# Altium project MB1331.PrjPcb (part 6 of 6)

## Sheet Power_MCU.SchDoc: MCU Power
size A4; Date: Not used; ApprovedBy: Not used; CheckedBy: Not used; Author: Not used; CompanyName: STMicroelectronics; DrawnBy: Not used; Engineer: Not used; Organization: Not used; Address1: Not used; Address2: Not used; Address3: Not used; Address4: Not used; DocumentNumber: Not used; Revision: Not used; SheetNumber: 21; SheetTotal: 23
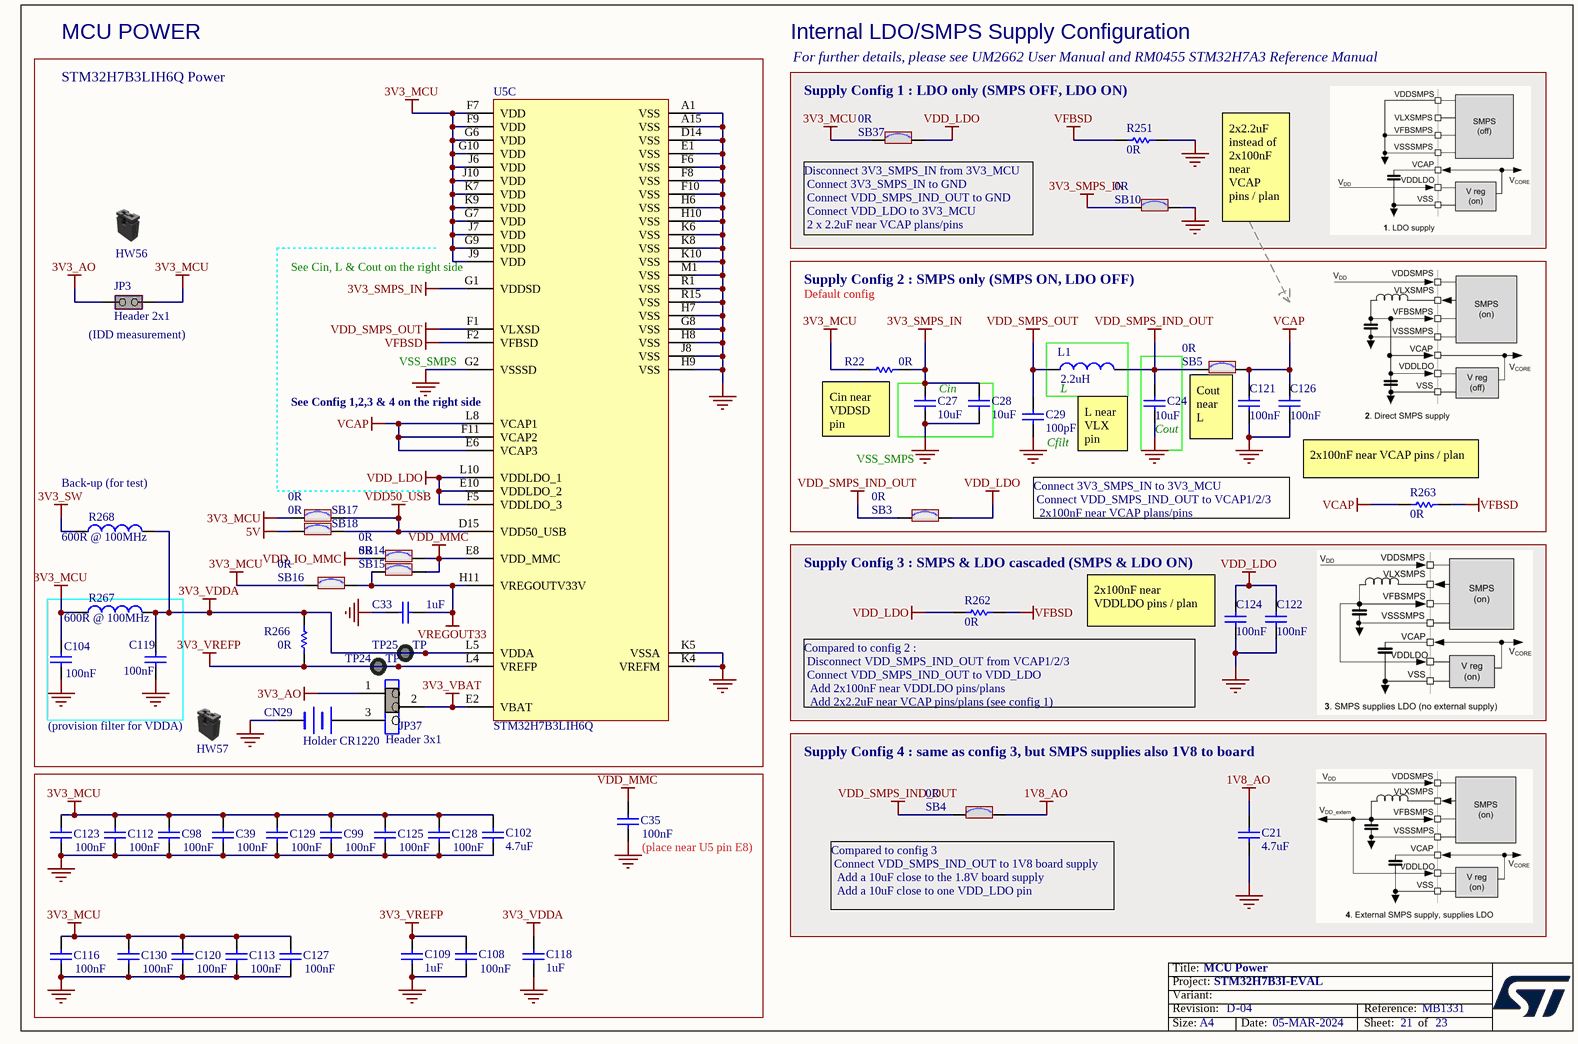
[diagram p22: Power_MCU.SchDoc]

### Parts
C21  value 4.7uF  [C0603]  (hidden comment: Capacitor)
C24  value 10uF  [C0603]  (hidden comment: Capacitor)
C27  value 10uF  [C0402]  (hidden comment: Capacitor)
C28  value 10uF  [C0402]  (hidden comment: Capacitor)
C29  value 100pF  [C0402]  (hidden comment: Capacitor)
C33  value 1uF  [C0603]  (hidden comment: Capacitor)
C35  value 100nF  [C0402]  (hidden comment: Capacitor)
C39  value 100nF  [C0402]  (hidden comment: Capacitor)
C98  value 100nF  [C0402]  (hidden comment: Capacitor)
C99  value 100nF  [C0402]  (hidden comment: Capacitor)
C102  value 4.7uF  [C0603]  (hidden comment: Capacitor)
C104  value 100nF  [C0402]  (hidden comment: Capacitor)
C108  value 100nF  [C0402]  (hidden comment: Capacitor)
C109  value 1uF  [C0402]  (hidden comment: Capacitor)
C112  value 100nF  [C0402]  (hidden comment: Capacitor)
C113  value 100nF  [C0402]  (hidden comment: Capacitor)
C116  value 100nF  [C0402]  (hidden comment: Capacitor)
C118  value 1uF  [C0402]  (hidden comment: Capacitor)
C119  value 100nF  [C0402]  (hidden comment: Capacitor)
C120  value 100nF  [C0402]  (hidden comment: Capacitor)
C121  value 100nF  [C0402]  (hidden comment: Capacitor)
C122  value 100nF  [C0402]  (hidden comment: Capacitor)
C123  value 100nF  [C0402]  (hidden comment: Capacitor)
C124  value 100nF  [C0402]  (hidden comment: Capacitor)
C125  value 100nF  [C0402]  (hidden comment: Capacitor)
C126  value 100nF  [C0402]  (hidden comment: Capacitor)
C127  value 100nF  [C0402]  (hidden comment: Capacitor)
C128  value 100nF  [C0402]  (hidden comment: Capacitor)
C129  value 100nF  [C0402]  (hidden comment: Capacitor)
C130  value 100nF  [C0402]  (hidden comment: Capacitor)
CN29  value Holder CR1220  [BAT_HARWIN_S8411-45R_SMD_2P]  (hidden comment: BATTERY HOLDER)
HW56  Shunt Black 2.54mm  (value not drawn)  (mechanical)
HW57  Shunt Black 2.54mm  (value not drawn)  (mechanical)
JP3  value Header 2x1  [CON_SAMTEC_TSW-102-07-G-S]  (hidden comment: Jumper_Header 2x1 Fitted)
JP37  value Header 3x1  [CON_SAMTEC_TSW-103-07-F-S]  (hidden comment: Jumper_Header 3x1 Fitted 1-2)
L1  value 2.2uH  [L0805_H0P9]  (hidden comment: Inductor)
R22  value 0R  [R0603]  (hidden comment: Resistor)
R251  value 0R  [R0402]  (hidden comment: Resistor)
R262  value 0R  [R0402]  (hidden comment: Resistor)
R263  value 0R  [R0402]  (hidden comment: Resistor)
R266  value 0R  [R0603]  (hidden comment: Resistor)
R267  value 600R @ 100MHz  [L0603]  (hidden comment: BEAD)
R268  value 600R @ 100MHz  [L0603]  (hidden comment: BEAD)
SB3  value 0R  [SOLDER-BRIDGE_R0603-0R]  (hidden comment: SB_ON)
SB4  value 0R  [SOLDER-BRIDGE_R0603-0R]  (hidden comment: SB_ON)
SB5  value 0R  [SOLDER-BRIDGE_R0603-0R]  (hidden comment: SB_ON)
SB10  value 0R  [SOLDER-BRIDGE_R0603-0R]  (hidden comment: SB_ON)
SB14  value 0R  [SOLDER-BRIDGE_R0603-0R]  (hidden comment: SB_ON)
SB15  value 0R  [SOLDER-BRIDGE_R0603-0R]  (hidden comment: SB_ON)
SB16  value 0R  [SOLDER-BRIDGE_R0603-0R]  (hidden comment: SB_ON)
SB17  value 0R  [SOLDER-BRIDGE_R0603-0R]  (hidden comment: SB_ON)
SB18  value 0R  [SOLDER-BRIDGE_R0603-0R]  (hidden comment: SB_ON)
SB37  value 0R  [SOLDER-BRIDGE_R0603-0R]  (hidden comment: SB_ON)
TP24  value TP  [TP_PTH_1MM_2MM]  (hidden comment: Test_Point_PTH_1mm_2mm)  (no BOM)
TP25  value TP  [TP_PTH_1MM_2MM]  (hidden comment: Test_Point_PTH_1mm_2mm)  (no BOM)
U5  value STM32H7B3LIH6Q  [ICC_TFBGA225_13X13_STM32H7B3NIH6Q_P080__SOCKET_IRONWOOD_CS1222291MF_REV-A_WITHOUT-3D-SOCKET]  (hidden comment: STM32H7B3NIH6Q)  (part C of 3)

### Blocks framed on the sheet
MCU POWER: C33 C104 C119 CN29 HW56 HW57 JP3 JP37 R266-R268 SB14-SB18 TP24 TP25 U5
Supply Config 1 : LDO only (SMPS OFF, LDO ON): R251 SB10 SB37
Supply Config 2 : SMPS only (SMPS ON, LDO OFF): C29 C121 C126 R22 R263 SB3 SB5
L: L1
Cin: C27 C28
Cout: C24
Supply Config 3 : SMPS & LDO cascaded (SMPS & LDO ON): C122 C124 R262
(place near U5 pin E8): C35 C39 C98 C99 C102 C108 C109 C112 C113 C116 C118 C120 C123 C125 C127-C130

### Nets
1V8_AO: C21.2 SB4.2
3V3_AO: JP3.1(COMMON) JP37.1
3V3_MCU: C39.1 C98.1 C99.1 C102.2 C104.1 C112.1 C113.1 C116.1 C120.1 C123.1 C125.1 C127.1 C128.1 C129.1 C130.1 JP3.2(NO) R22.2 R267.1 SB16.1 SB17.2 SB37.2 U5.F7(VDD) U5.F9(VDD) U5.G6(VDD) U5.G7(VDD) U5.G9(VDD) U5.G10(VDD) U5.J6(VDD) U5.J7(VDD) U5.J9(VDD) U5.J10(VDD) U5.K7(VDD) U5.K9(VDD)
3V3_SMPS_IN: C27.2 C28.2 R22.1 SB10.2 U5.G1(VDDSD)
3V3_SW: R268.1
3V3_VBAT: JP37.2 U5.E2(VBAT)
3V3_VDDA: C118.2 C119.1 R266.1 R267.2 R268.2 TP25.1 U5.L5(VDDA)
3V3_VREFP: C108.2 C109.2 R266.2 TP24.1 U5.L4(VREFP)
5V: SB18.2
GND: C21.1 C24.1 C27.1 C28.1 C29.1 C33.2 C35.2 C39.2 C98.2 C99.2 C102.1 C104.2 C108.1 C109.1 C112.2 C113.2 C116.2 C118.1 C119.2 C120.2 C121.2 C122.2 C123.2 C124.2 C125.2 C126.2 C127.2 C128.2 C129.2 C130.2 CN29.2(-) R251.2 SB10.1 U5.A1(VSS) U5.A15(VSS) U5.D14(VSS) U5.E1(VSS) U5.F6(VSS) U5.F8(VSS) U5.F10(VSS) U5.G2(VSSSD) U5.G8(VSS) U5.H6(VSS) U5.H7(VSS) U5.H8(VSS) U5.H9(VSS) U5.H10(VSS) U5.J8(VSS) U5.K4(VREFM) U5.K5(VSSA) U5.K6(VSS) U5.K8(VSS) U5.K10(VSS) U5.M1(VSS) U5.R1(VSS) U5.R15(VSS)
VCAP: C121.1 C126.1 R263.1 SB5.1 U5.E6(VCAP3) U5.F11(VCAP2) U5.L8(VCAP1)
VDD50_USB: SB17.1 SB18.1 U5.D15(VDD50_USB)
VDD_IO_MMC: SB14.1
VDD_LDO: C122.1 C124.1 R262.1 SB3.1 SB37.1 U5.E10(VDDLDO_2) U5.F5(VDDLDO_3) U5.L10(VDDLDO_1)
VDD_MMC: C35.1 SB14.2 SB15.1 U5.E8(VDD_MMC)
VDD_SMPS_IND_OUT: C24.2 L1.2 SB3.2 SB4.1 SB5.2
VDD_SMPS_OUT: C29.2 L1.1 U5.F1(VLXSD)
VFBSD: R251.1 R262.2 R263.2 U5.F2(VFBSD)
VREGOUT33: C33.1 SB15.2 SB16.2 U5.H11(VREGOUTV33V)
NetCN29_1: CN29.1(+) JP37.3

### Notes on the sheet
- Internal LDO/SMPS Supply Configuration
- STM32H7B3LIH6Q Power
- For further details, please see UM2662 User Manual and RM0455 STM32H7A3 Reference Manual
- (near SB37) Disconnect 3V3_SMPS_IN from 3V3_MCU
  Connect 3V3_SMPS_IN to GND
  Connect VDD_SMPS_IND_OUT to GND
  Connect VDD_LDO to 3V3_MCU
  2 x 2.2uF near VCAP plans/pins
- 2x2.2uF instead of 2x100nF near VCAP pins / plan
- (near U5) See Cin, L & Cout on the right side
- Default config
- (near JP3) (IDD measurement)
- (near U5) VSS_SMPS
- (near U5) See Config 1,2,3 & 4 on the right side
- (near R22) Cin near VDDSD pin
- (near C29) Cfilt
- L near VLX pin
- (near SB5) Cout near L
- (near R268) Back-up (for test)
- VSS_SMPS
- Connect 3V3_SMPS_IN to 3V3_MCU
  Connect VDD_SMPS_IND_OUT to VCAP1/2/3
  2x100nF near VCAP plans/pins
- 2x100nF near VCAP pins / plan
- (near C124) 2x100nF near VDDLDO pins / plan
- Compared to config 2 :
  Disconnect VDD_SMPS_IND_OUT from VCAP1/2/3
  Connect VDD_SMPS_IND_OUT to VDD_LDO
  Add 2x100nF near VDDLDO pins/plans
  Add 2x2.2uF near VCAP pins/plans (see config 1)
- (near HW57) (provision filter for VDDA)
- Supply Config 4 : same as config 3, but SMPS supplies also 1V8 to board
- (near SB4) Compared to config 3
  Connect VDD_SMPS_IND_OUT to 1V8 board supply
  Add a 10uF close to the 1.8V board supply
  Add a 10uF close to one VDD_LDO pin

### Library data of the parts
C21 C102 = MCD-04044: Capacitor, MLCC, 4.7uF, 10V, X5R, 20%, 0603, T=0.8mm; Manufacturer_Part_Number: C0603C475M8PAC7040; Manufacturer: KEMET CORPORATION; Part_Preference: Recommended; Component_Country_Of_Origin: Mexico; ShowFields: YES; ID: 6160
C24 = MCD-01341: Capacitor, MLCC, 10uF, 6V3, X5R, 20%, 0603, T=0,8mm; Manufacturer_Part_Number: GRM188R60J106ME47D; Manufacturer: MURATA; Part_Preference: Recommended; Provided_By: SUBCO; ECCN_US: EAR99; ECCN_EU: NEC; Component_Country_Of_Origin: Japan°°; ID: 3441; ShowFields: YES
C27 C28 = MCD-01716: Capacitor, MLCC, 10uF, 6V3, X5R, 20%, 0402, T=0.5mm; Manufacturer_Part_Number: CC0402MRX5R5BB106; Manufacturer: YAGEO; Part_Preference: Recommended; Provided_By: SUBCO; Component_Country_Of_Origin: China; ID: 3816; ShowFields: YES
C29 = MCD-00205: Capacitor, MLCC, 100pF, 50V, NPO, 5%, 0402, T=0,5mm; Manufacturer_Part_Number: CC0402JRNPO9BN101; Manufacturer: YAGEO; Part_Preference: Recommended; Provided_By: SUBCO; ECCN_US: EAR99; ECCN_EU: NEC; Component_Country_Of_Origin: China; ID: 2658; ShowFields: YES
C33 = MCD-00010: Capacitor, MLCC, 1uF, 16V, X5R, 10%, 0603, T=0,8mm; Manufacturer_Part_Number: CC0603KRX5R7BB105; Manufacturer: YAGEO; Part_Preference: Recommended; Provided_By: SUBCO; ECCN_US: EAR99; ECCN_EU: NEC; Component_Country_Of_Origin: China; ID: 2470; Order_Code_RS: 2370680; ShowFields: YES
C35 C39 C98 C99 C104 C108 C112 C113 C116 C119-C130 = MCD-00006: Capacitor, MLCC, 100nF, 16V, X7R, 10%, 0402, T=0.5mm; Manufacturer_Part_Number: CC0402KRX7R7BB104; Manufacturer: YAGEO; Alternate_Manufacturer_Part_Number: GCM155R71C104KA55D; Alternate_Manufacturer: MURATA; Part_Preference: Recommended; Partial_Alternate_Internal_Part_Number: MCD-03299; Provided_By: SUBCO; ECCN_US: EAR99; ECCN_EU: NEC; Component_Country_Of_Origin: China; ID: 2474; Order_Code_RS: 9402047; ShowFields: YES
C109 C118 = MCD-00095: Capacitor, MLCC, 1uF, 6V3, X5R, 10%, 0402, T=0,5mm; Manufacturer_Part_Number: GRM155R61E105KA12; Manufacturer: MURATA; Alternate_Manufacturer_Part_Number: GRM155R60J105KE19; Part_Preference: Recommended; Provided_By: SUBCO; ECCN_US: EAR99; ECCN_EU: NEC; Component_Country_Of_Origin: Japan°°; ID: 2772; Order_Code_RS: 2218855; ShowFields: YES
CN29 = MCD-00558: Battery Coin Cell holder, CR1220_12mm, Height 4.25mm; Part_Type: Connector; Manufacturer_Part_Number: S8411-45R; Manufacturer: HARWIN; Part_Preference: Recommended; Provided_By: SUBCO; Component_Country_Of_Origin: Taiwan; ID: 3187; ShowFields: YES
HW56 HW57 = MCD-00043: SHUNT 2.54mm BLACK; Part_Type: Misc; Manufacturer: SAMTEC; Alternate_Manufacturer_Part_Number: 316102S111A; Alternate_Manufacturer: JIUBABA; Full_Alternate_Internal_Part_Number: MCD-02388; Manufacturer_HQ_COO: Unknown; Part_Preference: Recommended; Partial_Alternate_Internal_Part_Number: MCD-01849; Value: SNT-100-BK-G; Provided_By: SUBCO; Alternate_EMS: A; Component_Country_Of_Origin: China, Costa Rica, Malaysia, USA, Vietnam; ID: 2551; Order_Code_RS: 158-7784; ShowFields: YES
JP3 = MCD-00683: Header, 2x1, 2,54mm, VR, TH, Height 5.84mm/2.54mm - Shunt Fitted by default; Part_Type: Connector; Manufacturer_Part_Number: TSW-102-07-G-S; Manufacturer: SAMTEC; Alternate_Manufacturer_Part_Number: 313102S111116; Alternate_Manufacturer: LIANYI; Full_Alternate_Internal_Part_Number: MCD-02389; Part_Preference: Recommended; Partial_Alternate_Internal_Part_Number: MCD-02957, MCD-03720; Provided_By: SUBCO; Component_Country_Of_Origin: China, Costa Rica, Malaysia, USA, Vietnam; ID: 3057; Order_Code_RS: 155-5312; ShowFields: YES
JP37 = MCD-00684: Header, 3x1, 2,54mm, VR, TH, Height 5.84mm/2.54mm - Shunt Fitted 1-2 by default; Part_Type: Connector; Manufacturer_Part_Number: TSW-103-07-F-S; Manufacturer: SAMTEC; Part_Preference: Recommended; Partial_Alternate_Internal_Part_Number: MCD-03595, MCD-03723; Provided_By: SUBCO; Alternate_EMS: A; Component_Country_Of_Origin: China, Costa Rica, Malaysia, USA, Vietnam; ID: 3059; Order_Code_RS: 161-2248; ShowFields: YES
L1 = MCD-01340: Inductor, 2.2uH, 20%, Isat 1.2A, DCR 0.228Ohm, 0805; Manufacturer_Part_Number: DFE201210U-2R2M=P2; Manufacturer: MURATA; Part_Preference: Recommended; Provided_By: SUBCO; Component_Country_Of_Origin: Japan°°; ID: 3440; ShowFields: YES
R22 R266 = MCD-00056: Resistor,0R,0603,5%,1/10W; Manufacturer_Part_Number: RC0603JR-070RL; Manufacturer: YAGEO; Part_Preference: Recommended; Provided_By: SUBCO; ECCN_US: EAR99; ECCN_EU: NEC; Component_Country_Of_Origin: China; ID: 2536; Order_Code_RS: 9233130RL; ShowFields: YES
R251 R262 R263 = MCD-00052: Resistor,0R,0402,5%,1/16W; Manufacturer_Part_Number: RC0402JR-070RL; Manufacturer: YAGEO; Part_Preference: Recommended; Provided_By: SUBCO; ECCN_US: EAR99; ECCN_EU: NEC; Component_Country_Of_Origin: China; ID: 2540; Order_Code_RS: 9232516RL; ShowFields: YES
R267 R268 = MCD-00047: SMD Chip ferrite bead, 600R@100MHz +/-25%, 350mA, 500mohm DC, 0603, T=0.8mm; Part_Type: Inductor; Manufacturer_Part_Number: FCM1608KF-601T03; Manufacturer: TAI-TECH; Part_Preference: Recommended; Partial_Alternate_Internal_Part_Number: MCD-02959; Provided_By: SUBCO; Component_Country_Of_Origin: Unknown; ID: 2546; ShowFields: YES
SB3-SB5 SB10 SB14-SB18 SB37 = MCD-00071: Solder Bridge ON; Part_Type: Resistor; Manufacturer_Part_Number: RC0603JR-070RL; Manufacturer: YAGEO; Manufacturer_HQ_COO: Unknown; Part_Preference: Recommended; Provided_By: SUBCO; Component_Country_Of_Origin: China; ID: 2521; Order_Code_RS: 199-5647; ShowFields: YES
TP24 TP25 = MCD-01506: Test Point trought hole 1mm/2mm; Part_Type: Misc; Part_Preference: Recommended; Component_Country_Of_Origin: Unknown; ID: 3606; ShowFields: YES
U5 = MCD-01929: STM32H7B3LIH6Q (crypto),TFBGA 225, 13x13 0.8; Part_Type: IC; Manufacturer: STMICROELECTRONICS; BMS_Part_Number: 9175358; Manufacturer_HQ_COO: EU; Part_Preference: Recommended; ECCN_US: 5A992C; ECCN_EU: 5A002A4; Provided_By: SUBCO with ST control; Component_Country_Of_Origin: Philippines; ID: 4029; Order_Code_RS: 201-4447; ShowFields: YES

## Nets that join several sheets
1V8_AO: Audio_Codec (SB25.1), Power_Board (SB22.2 TP12.1), USB_OTG_HS_externalPHY (R274.1), Power_MCU (C21.2 SB4.2)
1V8_SW: Audio_Codec (SB26.1), Power_Board (R4.1 SB19.2 TP10.1), USB_OTG_HS_externalPHY (R273.1)
2V8: Camera (8 pins), Power_Board (SB1.2 TP1.1)
3V3_AO: SDcard (10 pins), Camera (R217.2), MCU (R43.1 R279.1), Audio_Codec (SB27.1), DFSDM_Audio&Motor (CN4.2 CN4.19), LCD (C79.2 CN30.2), JTAG&Trace (9 pins), MCU_Clock&Reset (R31.1 SW1.2), Memory (49 pins), MFX (14 pins), MotorControl (8 pins), OCSPI (SB39.2 SB40.1), Peripherals (10 pins), Power_Board (6 pins), STLink_V3E_SWD (R146.2), ExtensionConnector (CN5.48 CN6.48 CN13.40), USB_OTG_FS (R193.2 R195.2 R196.2), USB_OTG_HS_externalPHY (6 pins), FDCAN&RS232 (6 pins), Power_MCU (JP3.1 JP37.1)
3V3_SW: SDcard (C94.2 C95.2 CN3.4), Audio_Codec (SB28.1), Power_Board (6 pins), USB_OTG_HS_externalPHY (R47.1), STMPS2&PT100 (5 pins), Power_MCU (R268.1)
5V: LCD (R159.2), MotorControl (CN1.25), Peripherals (U24.42), Power_Board (17 pins), STLink_V3E_SWD (R153.2), ExtensionConnector (CN5.60 CN6.60), USB_OTG_FS (U29.5), USB_OTG_HS_externalPHY (C111.1 U7.21 U39.5), FDCAN&RS232 (C197.1 U28.3), Power_MCU (SB18.2)
5V_D: Power_Board (JP29.9), STLink_V3E_SWD (D7.1), ExtensionConnector (CN5.49 CN6.49)
5V_EXT: Power_Board (C157.1 JP29.3 L2.2), STLink_V3E_SWD (D4.1)
5V_STLK: Power_Board (JP29.1), STLink_V3E_SWD (C71.2 TP21.1 U22.1)
5V_USB_CHGR: Power_Board (JP29.11), STLink_V3E_SWD (11 pins)
5V_USB_FS: Power_Board (JP29.7), STLink_V3E_SWD (D6.1), USB_OTG_FS (R182.2)
5V_USB_HS: Power_Board (JP29.5), STLink_V3E_SWD (D5.1), USB_OTG_HS_externalPHY (R44.2)
GND: Top (8 pins), SDcard (24 pins), Camera (15 pins), MCU (C30.2 C97.2), Audio_Codec (36 pins), DFSDM_Audio&Motor (CN4.1 CN4.20), LCD (26 pins), JTAG&Trace (30 pins), MCU_Clock&Reset (12 pins), Memory (49 pins), MFX (15 pins), MotorControl (35 pins), OCSPI (14 pins), Peripherals (17 pins), Power_Board (35 pins), STLink_V3E_SWD (92 pins), ExtensionConnector (20 pins), USB_OTG_FS (14 pins), USB_OTG_HS_externalPHY (27 pins), FDCAN&RS232 (20 pins), STMPS2&PT100 (20 pins), Power_MCU (56 pins)
VDD_IO_MMC: SDcard (5 pins), Power_Board (C4.2 R5.2), Power_MCU (SB14.1)
A0: MCU (R339.2), Memory (U12.E2 U16.G8 U17.A3)
A1: MCU (R335.2), Memory (U12.D2 U16.G9 U17.A4)
A2: MCU (R331.2), Memory (U12.C2 U16.F7 U17.A5)
A3: MCU (R74.2), Memory (U12.A2 U16.F3 U17.B3)
A4: MCU (R66.2), Memory (U12.B2 U16.G1 U17.B4)
A5: MCU (R65.2), Memory (U12.D3 U16.G2 U17.C3)
A6: MCU (R326.2), Memory (U12.C3 U16.G3 U17.C4)
A7: MCU (R325.2), Memory (U12.A3 U16.H1 U17.D4)
A8: MCU (R70.2), Memory (U12.B6 U16.H2 U17.H2)
A9: MCU (R103.2), Memory (U12.A6 U16.J3 U17.H3)
A10: MCU (R73.1), Memory (U12.C6 U16.G7 U17.H4)
A11: MCU (R333.1), Memory (U12.D6 U16.H9 U17.H5)
A12: MCU (R380.1), Memory (U12.B7 U17.G3)
A13: MCU (R374.1), Memory (U12.A7 U17.G4)
A14: MCU (R369.1), Memory (U12.C7 U16.J7 U17.F3)
A15: MCU (R366.1), Memory (U12.D7 U16.H8 U17.F4)
A16: MCU (R359.2), Memory (U12.E7 U17.E4)
A17: MCU (R362.2), Memory (U12.B3 U17.D3)
A18: MCU (R375.2), Memory (U12.C4 U17.H1)
A19: MCU (R97.2), Memory (R346.2 U12.D5 U17.G2)
A20: MCU (R88.2), Memory (R92.2 U12.D4 U17.H6)
A21: MCU (R324.2), Memory (R336.2 U12.C5)
A22: MCU (R78.2), Memory (R86.2 U12.B8)
A23: MCU (R342.2), Memory (R107.2 U12.C8)
ADC_IN_N: MCU (R250.1), Audio_Codec (C106.2 R328.1)
ADC_IN_P: MCU (R244.1), Audio_Codec (C103.1 R329.1)
BOOT0: MCU (U5.C5), MCU_Clock&Reset (JP22.2 R3.1)
BOOTLOADER_BOOT0: MCU_Clock&Reset (D1.1), FDCAN&RS232 (U9.20)
BOOTLOADER_RST: MCU_Clock&Reset (JP24.2), FDCAN&RS232 (U9.16)
CTP_INT: MCU (U5.M4), LCD (CN30.10), ExtensionConnector (CN6.25)
CTP_RST: MCU (R281.1), LCD (R156.1)
D0: MCU (R391.2), Memory (U12.E3 U16.R8 U17.B6)
D1: MCU (R127.2), Memory (U12.H3 U16.N7 U17.C5)
D2: MCU (R119.2), Memory (U12.E4 U16.R9 U17.C6)
D3: MCU (R373.2), Memory (U12.H4 U16.N8 U17.D5)
D4: MCU (R338.2), Memory (U12.H5 U16.P9 U17.E5)
D5: MCU (R96.2), Memory (U12.E5 U16.M8 U17.F5)
D6: MCU (R87.2), Memory (U12.H6 U16.M7 U17.F6)
D7: MCU (R341.2), Memory (U12.E6 U16.L8 U17.G6)
D8: MCU (R102.2), Memory (U12.F3 U16.L2 U17.B1)
D9: MCU (R345.2), Memory (U12.G3 U16.M3 U17.C1)
D10: MCU (R353.2), Memory (U12.F4 U16.M2 U17.C2)
D11: MCU (R105.2), Memory (U12.G4 U16.P1 U17.D2)
D12: MCU (R348.2), Memory (U12.F5 U16.N2 U17.E2)
D13: MCU (R384.2), Memory (U12.G6 U16.R1 U17.F2)
D14: MCU (R385.2), Memory (U12.F6 U16.N3 U17.F1)
D15: MCU (R381.2), Memory (U12.G7 U16.R2 U17.G1)
D16: MCU (R358.1), Memory (U16.E8)
D17: MCU (R365.1), Memory (U16.D7)
D18: MCU (R361.1), Memory (U16.D8)
D19: MCU (R370.1), Memory (U16.B9)
D20: MCU (R371.1), Memory (U16.C8)
D21: MCU (R131.1), Memory (U16.A9)
D22: MCU (R387.1), Memory (U16.C7)
D23: MCU (R382.1), Memory (U16.A8)
D24: MCU (R128.2), Memory (U16.A2)
D25: MCU (R124.1), Memory (U16.C3)
D26: MCU (R121.1), Memory (U16.A1)
D27: MCU (R378.1), Memory (U16.C2)
D28: MCU (R356.1), Memory (U16.B1)
D29: MCU (R347.1), Memory (U16.D2)
D30: MCU (R351.2), Memory (U16.D3)
D31: MCU (R357.2), Memory (U16.E2)
DCMI_D0: Camera (CN2.23), MCU (JP32.1)
DCMI_D1: Camera (CN2.24), MCU (R113.1)
DCMI_D2: Camera (CN2.25), MCU (R118.1)
DCMI_D3: Camera (CN2.26), MCU (JP1.1)
DCMI_D4: Camera (CN2.27), MCU (R116.1)
DCMI_D5: Camera (CN2.28), MCU (R48.2)
DCMI_D6: Camera (CN2.29), MCU (R110.2)
DCMI_D7: Camera (CN2.30), MCU (R104.1)
DCMI_HSYNC: Camera (CN2.31), MCU (JP7.3)
DCMI_PIXCLK: Camera (CN2.33), MCU (JP6.1)
DCMI_VSYNC: Camera (CN2.32), MCU (JP17.1)
DFSDM1_2_CKOUT: MCU (R271.1), DFSDM_Audio&Motor (CN4.3 CN4.4), STMPS2&PT100 (R208.2)
DFSDM1_2_DATIN1: MCU (JP19.1), DFSDM_Audio&Motor (CN4.6), STMPS2&PT100 (R205.2)
DFSDM1_DATIN3: MCU (JP35.3), DFSDM_Audio&Motor (CN4.5)
DFSDM1_DATIN5: MCU (U5.A4), DFSDM_Audio&Motor (CN4.7), ExtensionConnector (CN6.17), STMPS2&PT100 (R33.2)
DFSDM1_DATIN7: MCU (R233.2), DFSDM_Audio&Motor (CN4.8)
FDCAN_RX: MCU (SB36.1), FDCAN&RS232 (U28.4)
FDCAN_TX: MCU (SB35.1), FDCAN&RS232 (U28.1)
FMC_NBL0: MCU (R117.2), Memory (U16.K9 U17.A1)
FMC_NBL1: MCU (R114.2), Memory (R109.2 U16.K1 U17.B2)
FMC_NBL2: MCU (R350.2), Memory (R143.1 U16.F8)
FMC_NBL3: MCU (R344.2), Memory (R134.1 U16.F2)
FMC_NE1: MCU (JP35.1), Memory (R91.1 U12.F2)
FMC_NE3: MCU (JP2.1 JP12.3), Memory (R142.1 U17.B5)
FMC_NOE: MCU (R368.2), Memory (U12.G2 U17.A2)
FMC_NWAIT: MCU (JP32.3), Memory (R79.1 U12.A4)
FMC_NWE: MCU (R364.2), Memory (U12.A5 U17.G5)
GNDDetect: JTAG&Trace (CN16.11 R164.2 U47.5), STLink_V3E_SWD (U21.K13)
I2C2_SCL: Camera (Q1.3 R206.1), MCU (R275.1 R279.2), Audio_Codec (U48.3), LCD (CN30.5), MFX (R161.1), Peripherals (CN24.6 U24.5)
I2C2_SDA: Camera (Q2.3 R207.1), MCU (R35.1 R43.2), Audio_Codec (U48.2), LCD (CN30.3), MFX (R162.1), Peripherals (CN24.8 U24.4)
I2S6_CK: MCU (JP11.1), Audio_Codec (R135.2)
I2S6_EXT_SD: MCU (JP6.3 JP8.1), Audio_Codec (R140.2)
I2S6_MCK: MCU (JP9.1), Audio_Codec (R139.2)
I2S6_SD: MCU (JP18.2), Audio_Codec (R136.2)
I2S6_WS: MCU (JP7.1), Audio_Codec (R137.2)
JTAG_HOST_NRST: JTAG&Trace (5 pins), STLink_V3E_SWD (R398.2)
JTAG_TCK: JTAG&Trace (6 pins), Peripherals (R406.1), STLink_V3E_SWD (R401.2)
JTAG_TDO: JTAG&Trace (7 pins), STLink_V3E_SWD (R399.2)
JTAG_TMS: JTAG&Trace (6 pins), Peripherals (R407.1), STLink_V3E_SWD (R409.2)
LCD_B0: MCU (R259.2), LCD (CN23.22)
LCD_B1: MCU (R264.2), LCD (CN23.23)
LCD_B2: MCU (R269.2), LCD (CN23.24)
LCD_B3: MCU (R276.2), LCD (CN23.25)
LCD_B4: MCU (R256.2), LCD (CN23.26)
LCD_B5: MCU (R254.2), LCD (CN23.27)
LCD_B6: MCU (R249.2), LCD (CN23.28)
LCD_B7: MCU (R243.2), LCD (CN23.29)
LCD_BL_CTRL: MCU (R236.1 R258.2), LCD (CN23.39)
LCD_CLK: MCU (R226.2), LCD (C200.2 R285.1)
LCD_DE: MCU (R248.2), LCD (CN23.33)
LCD_G0: MCU (R315.2), LCD (CN23.13)
LCD_G1: MCU (R306.2), LCD (CN23.14)
LCD_G2: MCU (R310.2), LCD (CN23.15)
LCD_G3: MCU (R312.2), LCD (CN23.16)
LCD_G4: MCU (R302.2), LCD (CN23.17)
LCD_G5: MCU (R305.2), LCD (CN23.18)
LCD_G6: MCU (R299.2), LCD (CN23.19)
LCD_G7: MCU (R303.2), LCD (CN23.20)
LCD_HSYNC: MCU (R215.2), LCD (CN23.31)
LCD_R0: MCU (R290.2), LCD (CN23.4)
LCD_R1: MCU (R293.2), LCD (CN23.5)
LCD_R2: MCU (R270.2), LCD (CN23.6)
LCD_R3: MCU (R260.2), LCD (CN23.7)
LCD_R4: MCU (R291.2), LCD (CN23.8)
LCD_R5: MCU (R265.2), LCD (CN23.9)
LCD_R6: MCU (R313.2), LCD (CN23.10)
LCD_R7: MCU (R317.2), LCD (CN23.11)
LCD_RESET: MCU (R240.1), LCD (R126.1)
LCD_VSYNC: MCU (R214.2), LCD (CN23.32)
MCO1: MCU (R308.1), USB_OTG_HS_externalPHY (R39.1)
MOTOR_ADC1_INP6: MCU (R72.1), MotorControl (C17.2 CN1.14 R7.2)
MOTOR_ADC2_INP1: MCU (R219.1), MotorControl (C12.2 CN1.26)
MOTOR_ADC12_INP4: MCU (R277.1), MotorControl (C13.2 CN1.24)
MOTOR_ADC12_INP7: MCU (R67.1), MotorControl (C14.2 CN1.19)
MOTOR_ADC12_INP8: MCU (R282.1), MotorControl (C8.2 CN1.32)
MOTOR_ADC12_INP10: MCU (R253.1), MotorControl (C16.2 CN1.15)
MOTOR_ADC12_INP11: MCU (R210.1), MotorControl (C15.2 CN1.17)
MOTOR_DFSDM1_2_CKIN1: MCU (R314.1), DFSDM_Audio&Motor (CN4.14)
MOTOR_DFSDM1_CKIN0: MCU (R246.1), DFSDM_Audio&Motor (CN4.17)
MOTOR_DFSDM1_CKIN2: MCU (R50.1), DFSDM_Audio&Motor (CN4.18)
MOTOR_DFSDM1_CKIN3: MCU (R123.1), DFSDM_Audio&Motor (CN4.13)
MOTOR_DFSDM1_CKIN4: MCU (R284.1), DFSDM_Audio&Motor (CN4.11)
MOTOR_DFSDM1_CKIN5: MCU (R238.1), DFSDM_Audio&Motor (CN4.16)
MOTOR_DFSDM1_CKIN7: MCU (R120.1), DFSDM_Audio&Motor (CN4.12)
MOTOR_DFSDM1_DATIN0: MCU (R209.1), DFSDM_Audio&Motor (CN4.9)
MOTOR_DFSDM1_DATIN2: MCU (R55.1), DFSDM_Audio&Motor (CN4.10)
MOTOR_DFSDM1_DATIN4: MCU (R95.1), DFSDM_Audio&Motor (CN4.15)
MOTOR_TIM1_BKIN: MCU (R349.1), MotorControl (C18.2 CN1.1 R9.1)
MOTOR_TIM1_CH1: MCU (R301.1), MotorControl (CN1.3)
MOTOR_TIM1_CH1N: MCU (R81.1), MotorControl (CN1.5)
MOTOR_TIM1_CH2: MCU (R294.1), MotorControl (CN1.7)
MOTOR_TIM1_CH2N: MCU (R304.1), MotorControl (CN1.9)
MOTOR_TIM1_CH3: MCU (R288.1), MotorControl (CN1.11)
MOTOR_TIM1_CH3N: MCU (R309.1), MotorControl (CN1.13)
MOTOR_TIM2_CH1: MCU (R213.1), MotorControl (C7.2 CN1.31 SB2.1)
MOTOR_TIM2_CH2: MCU (R235.1), MotorControl (C5.2 CN1.33)
MOTOR_TIM2_CH3: MCU (R239.1), MotorControl (C6.2 CN1.34)
MOTOR_TIM15_BKIN: MCU (R278.1), MotorControl (C10.2 CN1.30 R8.1)
MOTOR_TIM15_CH1: MCU (R323.1), MotorControl (C11.2 CN1.27)
MOTOR_TIM15_CH2: MCU (R330.1), MotorControl (C9.2 CN1.29)
NetB4_1: MCU (R363.1), MotorControl (B4.1 C82.2 R185.1 U49.6)
NetB4_2: MCU (R360.1), MotorControl (B4.2 C81.2 R184.1 U49.5)
NetB4_3: MCU (R367.1), MotorControl (B4.3 C80.2 R183.1 U49.4)
NetB4_4: MCU (R389.1), MotorControl (B4.4 C83.2 R186.1 U49.1)
NetB4_6: MCU (R386.1), MotorControl (B4.6 C84.2 R187.1 U49.3)
NJTRST: MCU (JP8.3), JTAG&Trace (R252.2)
NRST: MCU (U5.K3), LCD (R125.1 R155.1), JTAG&Trace (R218.2), MCU_Clock&Reset (5 pins), MFX (D3.2), OCSPI (R106.2 R321.2 SB21.1 SB38.1), Peripherals (SB45.2), ExtensionConnector (R225.1), USB_OTG_HS_externalPHY (SB13.2)
OCSPI1_CLK: MCU (R283.1), OCSPI (U11.B2)
OCSPI1_DQS: MCU (R286.1), OCSPI (U11.C3)
OCSPI1_IO0: MCU (R237.2), OCSPI (U11.D3)
OCSPI1_IO1: MCU (R241.2), OCSPI (U11.D2)
OCSPI1_IO2: MCU (R230.2), OCSPI (U11.C4)
OCSPI1_IO3: MCU (R234.2), OCSPI (U11.D4)
OCSPI1_IO4: MCU (R216.1), OCSPI (U11.D5)
OCSPI1_IO5: MCU (R272.1), OCSPI (U11.E3)
OCSPI1_IO6: MCU (JP4.1), OCSPI (U11.E2)
OCSPI1_IO7: MCU (R300.1), OCSPI (U11.E1)
OCSPI1_NCS: MCU (JP23.1), OCSPI (CN10.6 R355.2 U11.C2)
OCSPI2_CLK_N: MCU (R318.1), OCSPI (CN10.15)
OCSPI2_CLK_P: MCU (R319.1), OCSPI (CN10.17)
OCSPI2_DQS: MCU (R354.1), OCSPI (CN10.11)
OCSPI2_IO0: MCU (R98.1), OCSPI (CN10.3)
OCSPI2_IO1: MCU (R89.1), OCSPI (CN10.5)
OCSPI2_IO2: MCU (R82.1), OCSPI (CN10.7)
OCSPI2_IO3: MCU (R75.1), OCSPI (CN10.9)
OCSPI2_IO4: MCU (R76.1), OCSPI (CN10.8)
OCSPI2_IO5: MCU (R77.1), OCSPI (CN10.10)
OCSPI2_IO6: MCU (R115.1), OCSPI (CN10.12)
OCSPI2_IO7: MCU (R257.1), OCSPI (CN10.14)
OCSPI2_NCS: MCU (R287.1), OCSPI (CN10.1 R111.2)
PA0: MCU (C30.1 R213.2 R229.2 U5.P1), ExtensionConnector (CN6.8)
PA0_C: MCU (JP5.2 R244.2 U5.P3), ExtensionConnector (CN6.16)
PA0_WAKEUP: MCU (R229.1), MFX (R170.2), Peripherals (B2.3 B2.4 R172.2 U32.1)
PA1: MCU (R235.2 R236.2 U5.P2), ExtensionConnector (CN6.12)
PA1_C: MCU (R250.2 U5.R3), ExtensionConnector (CN6.18)
PA2: MCU (JP40.2 R239.2 R240.2 U5.R2), ExtensionConnector (CN6.14)
PA3: MCU (JP9.2 JP39.2 R258.1 U5.R4), ExtensionConnector (CN6.26)
PA4: MCU (JP7.2 R108.2 U5.L6), ExtensionConnector (CN6.21)
PA5: MCU (JP11.2 U5.N5), ExtensionConnector (CN6.31)
PA6: MCU (JP6.2 R349.2 U5.P5), ExtensionConnector (CN5.12)
PA7: MCU (R67.2 R322.2 U5.R5), ExtensionConnector (CN12.2)
PA8: MCU (R301.2 R308.2 U5.G11), ExtensionConnector (CN6.53)
PA9: MCU (R60.2 R294.2 U5.F12), ExtensionConnector (CN5.42)
PA10: MCU (R58.2 R288.2 U5.E13), ExtensionConnector (CN5.40)
PA11: MCU (R63.2 U5.C15), ExtensionConnector (CN5.43)
PA12: MCU (R61.2 U5.C14), ExtensionConnector (CN5.41)
PA13: MCU (U5.E12), JTAG&Trace (R57.2), ExtensionConnector (CN5.38)
PA14: MCU (U5.B13), JTAG&Trace (R59.2), ExtensionConnector (CN5.37)
PA15: MCU (U5.C12), JTAG&Trace (R53.2), ExtensionConnector (CN5.36)
PB0: MCU (JP10.1 R271.2 U5.P6), ExtensionConnector (CN6.28)
PB1: MCU (R296.2 U5.L7), ExtensionConnector (CN6.43)
PB2: MCU (R283.2 U5.R6), ExtensionConnector (CN6.32)
PB3: MCU (U5.C6), JTAG&Trace (R32.2), ExtensionConnector (CN5.16)
PB4: MCU (JP8.2 U5.B5), ExtensionConnector (CN5.14)
PB5: MCU (JP16.2 JP18.1 U5.E7), ExtensionConnector (CN6.46)
PB7: MCU (R29.2 R238.2 U5.D6), ExtensionConnector (CN5.13)
PB8: MCU (R110.1 R120.2 U5.B4), ExtensionConnector (CN5.11)
PB9: MCU (R104.2 R233.1 U5.A3), ExtensionConnector (CN5.9)
PB10: MCU (R292.2 U5.R13), ExtensionConnector (CN6.42)
PB11: MCU (R295.2 U5.P13), ExtensionConnector (CN6.44)
PB12: MCU (JP19.2 U5.N14), ExtensionConnector (CN6.52)
PB13: MCU (R314.2 R316.2 U5.M13), ExtensionConnector (CN6.58)
PB14: MCU (JP21.2 R304.2 U5.M14), ExtensionConnector (CN6.54)
PB15: MCU (JP20.2 R309.2 U5.M15), ExtensionConnector (CN6.56)
PC0: MCU (R246.2 R253.2 R255.2 U5.L3), ExtensionConnector (CN6.20)
PC1: MCU (R209.2 R210.2 R216.2 U5.M2), ExtensionConnector (CN6.1)
PC2: MCU (R245.2 U5.J5), ExtensionConnector (CN6.15)
PC2_C: MCU (U5.N1), ExtensionConnector (CN6.2)
PC3: MCU (R261.2 U5.N3), ExtensionConnector (CN6.23)
PC3_C: MCU (R219.2 U5.N2), ExtensionConnector (CN6.4)
PC4: MCU (R50.2 R277.2 R281.2 U5.M6), ExtensionConnector (CN6.33)
PC5: MCU (R55.2 R282.2 R286.2 U5.N6), ExtensionConnector (CN6.35)
PC6: MCU (JP32.2 U5.F14), ExtensionConnector (CN13.6)
PC7: MCU (JP35.2 R113.2 U5.E15), ExtensionConnector (CN13.24)
PC8: MCU (JP12.2 U5.F13), ExtensionConnector (CN5.44)
PC9: MCU (R62.2 U5.E14), ExtensionConnector (CN5.45)
PC10: MCU (R56.2 U5.A13), ExtensionConnector (CN5.35)
PC11: MCU (R51.2 U5.D11), ExtensionConnector (CN5.34)
PC12: MCU (R54.2 U5.B12), ExtensionConnector (CN5.33)
PC13: MCU (C97.1 R16.2 U5.F4), ExtensionConnector (CN5.6)
PC14: MCU (R23.2 U5.D1), ExtensionConnector (SB8.2)
PC14-OSC32_IN: MCU (R23.1), MCU_Clock&Reset (C25.2 X2.2)
PC15: MCU (R24.2 U5.D2), ExtensionConnector (SB9.1)
PC15-OSC32_OUT: MCU (R24.1), MCU_Clock&Reset (C26.2 X2.1)
PD0: MCU (R119.1 U5.C11), ExtensionConnector (CN13.31)
PD1: MCU (R373.1 U5.A12), ExtensionConnector (CN13.32)
PD2: MCU (R49.1 R278.2 U5.B11), ExtensionConnector (CN5.31)
PD3: MCU (R48.1 U5.D10), ExtensionConnector (CN5.32)
PD4: MCU (R367.2 R368.1 U5.A11), ExtensionConnector (CN13.28)
PD5: MCU (R363.2 R364.1 U5.C10), ExtensionConnector (CN13.26)
PD6: MCU (JP4.2 R284.2 U5.B10), ExtensionConnector (CN6.36)
PD7: MCU (R289.1 U5.A10), ExtensionConnector (CN6.38)
PD8: MCU (R123.2 R384.1 U5.L12), ExtensionConnector (CN12.35)
PD9: MCU (R385.1 U5.N15), ExtensionConnector (CN12.37)
PD10: MCU (R381.1 U5.L13), ExtensionConnector (CN12.36)
PD11: MCU (R359.1 U5.L14), ExtensionConnector (CN12.21)
PD12: MCU (R362.1 U5.L15), ExtensionConnector (CN12.23)
PD13: MCU (R375.1 U5.K11), ExtensionConnector (CN12.31)
PD14: MCU (R391.1 U5.K12), ExtensionConnector (CN12.39)
PD15: MCU (R127.1 U5.K13), ExtensionConnector (CN12.38)
PDR_ON: MCU (U5.D5), MCU_Clock&Reset (R30.1 R31.2)
PE0: MCU (R117.1 U5.B3), ExtensionConnector (CN13.25)
PE1: MCU (R114.1 U5.C4), ExtensionConnector (CN13.23)
PE2: MCU (R101.2 R342.1 R343.2 U5.E5), ExtensionConnector (CN13.16)
PE3: MCU (5 pins), ExtensionConnector (CN13.13)
PE4: MCU (5 pins), ExtensionConnector (CN13.11)
PE5: MCU (6 pins), ExtensionConnector (CN13.4)
PE6: MCU (6 pins), ExtensionConnector (CN13.7)
PE7: MCU (R338.1 U5.M9), ExtensionConnector (CN12.11)
PE8: MCU (R81.2 R96.1 U5.R11), ExtensionConnector (CN12.14)
PE9: MCU (R87.1 U5.P11), ExtensionConnector (CN12.12)
PE10: MCU (R95.2 R341.1 U5.N11), ExtensionConnector (CN12.13)
PE11: MCU (R102.1 U5.R12), ExtensionConnector (CN12.16)
PE12: MCU (R345.1 U5.L9), ExtensionConnector (CN12.15)
PE13: MCU (R353.1 U5.M10), ExtensionConnector (CN12.19)
PE14: MCU (R105.1 U5.N10), ExtensionConnector (CN12.20)
PE15: MCU (R348.1 U5.P12), ExtensionConnector (CN12.17)
PF0: MCU (R98.2 R339.1 U5.G4), ExtensionConnector (CN13.14)
PF1: MCU (R89.2 R335.1 U5.G3), ExtensionConnector (CN13.12)
PF2: MCU (R82.2 R331.1 U5.H1), ExtensionConnector (CN13.8)
PF3: MCU (R74.1 R75.2 U5.J1), ExtensionConnector (CN13.5)
PF4: MCU (R66.1 R319.2 U5.H3), ExtensionConnector (CN13.3)
PF5: MCU (R65.1 R318.2 U5.J2), ExtensionConnector (CN13.1)
PF6: MCU (R234.1 U5.J3), ExtensionConnector (CN6.9)
PF7: MCU (R230.1 U5.J4), ExtensionConnector (CN6.7)
PF8: MCU (R237.1 U5.K1), ExtensionConnector (CN6.11)
PF9: MCU (R241.1 U5.K2), ExtensionConnector (CN6.13)
PF10: SDcard (JP15.1 R15.1), MCU (U5.M3), ExtensionConnector (CN5.7)
PF11: MCU (R332.1 U5.N8), ExtensionConnector (CN12.8)
PF12: MCU (R72.2 R326.1 U5.R9), ExtensionConnector (CN12.5)
PF13: MCU (R325.1 U5.M8), ExtensionConnector (CN12.3)
PF14: MCU (R70.1 U5.P9), ExtensionConnector (CN12.4)
PF15: MCU (R103.1 U5.N9), ExtensionConnector (CN12.18)
PG0: MCU (R73.2 R76.2 U5.R10), ExtensionConnector (CN12.6)
PG1: MCU (R77.2 R333.2 U5.P10), ExtensionConnector (CN12.7)
PG2: MCU (R380.2 U5.H13), ExtensionConnector (CN12.33)
PG3: MCU (R374.2 U5.G15), ExtensionConnector (CN12.34)
PG4: MCU (R369.2 U5.H12), ExtensionConnector (CN12.28)
PG5: MCU (R366.2 U5.G14), ExtensionConnector (CN12.25)
PG6: MCU (JP23.2 U5.G13), ExtensionConnector (CN6.57)
PG7: MCU (JP14.1 U5.G12), ExtensionConnector (CN5.46)
PG8: MCU (R132.2 U5.F15), ExtensionConnector (CN12.40)
PG9: MCU (JP17.2 U5.A9), ExtensionConnector (CN6.51)
PG10_E: MCU (R115.2 R118.2 R280.1), ExtensionConnector (CN13.27)
PG11: MCU (JP1.2 R257.2 U5.B8), ExtensionConnector (CN6.22)
PG12: MCU (R122.2 R287.2 U5.C8), ExtensionConnector (CN6.34)
PG13: MCU (U5.D8), Peripherals (R178.2), ExtensionConnector (CN5.22)
PG14: MCU (R300.2 U5.A7), ExtensionConnector (CN6.47)
PG15: MCU (R352.2 R354.2 U5.A5), ExtensionConnector (CN13.19)
PH0: MCU (U5.L1), MCU_Clock&Reset (R21.2), ExtensionConnector (SB7.1)
PH1: MCU (U5.L2), MCU_Clock&Reset (R20.2), ExtensionConnector (SB6.2)
PH3: MCU (R272.2 U5.N4), ExtensionConnector (CN6.27)
PH4: MCU (R275.2 U5.M5), ExtensionConnector (CN6.29)
PH5: MCU (R35.2 U5.P4), ExtensionConnector (CN6.24)
PH6: MCU (R68.2 U5.M11), ExtensionConnector (CN12.1)
PH7: MCU (R320.2 U5.R14), ExtensionConnector (CN13.2)
PH8: MCU (R358.2 U5.P14), ExtensionConnector (CN12.22)
PH9: MCU (R365.2 U5.N13), ExtensionConnector (CN12.26)
PH10: MCU (R361.2 U5.M12), ExtensionConnector (CN12.24)
PH11: MCU (R370.2 U5.P15), ExtensionConnector (CN12.27)
PH12: MCU (R371.2 U5.L11), ExtensionConnector (CN12.32)
PH13: MCU (R131.2 R389.2 U5.D13), ExtensionConnector (CN13.39)
PH14: MCU (R387.2 U5.B15), ExtensionConnector (CN13.38)
PH15: MCU (R382.2 U5.B14), ExtensionConnector (CN13.36)
PI0: MCU (R128.1 R386.2 U5.C13), ExtensionConnector (CN13.37)
PI1: MCU (R124.2 U5.E11), ExtensionConnector (CN13.35)
PI2: MCU (R121.2 U5.D12), ExtensionConnector (CN13.33)
PI3: MCU (R378.2 U5.A14), ExtensionConnector (CN13.34)
PI4: MCU (R350.1 U5.A2), ExtensionConnector (CN13.17)
PI5: MCU (R344.1 U5.B2), ExtensionConnector (CN13.15)
PI6: MCU (R356.2 U5.C3), ExtensionConnector (CN13.22)
PI7: MCU (R347.2 U5.D4), ExtensionConnector (CN13.18)
PI8: MCU (U5.C1), MFX (R168.1), ExtensionConnector (CN5.8)
PI9: MCU (R351.1 R360.2 U5.E3), ExtensionConnector (CN13.20)
PI10: MCU (R357.1 U5.F3), ExtensionConnector (CN13.21)
PI11: MCU (R297.1 U5.G5), ExtensionConnector (CN6.45)
PI12: MCU (R215.1 U5.H2), ExtensionConnector (CN5.1)
PI13: MCU (R214.1 U5.H5), ExtensionConnector (CN5.2)
PI14: MCU (R226.1 U5.H4), ExtensionConnector (CN5.5)
PI15: MCU (R290.1 U5.M7), ExtensionConnector (CN6.37)
PJ0: MCU (R293.1 U5.N7), ExtensionConnector (CN6.41)
PJ1: MCU (R270.1 U5.P7), ExtensionConnector (CN5.27)
PJ2: MCU (R260.1 U5.R7), ExtensionConnector (CN5.23)
PJ3: MCU (R291.1 U5.R8), ExtensionConnector (CN6.40)
PJ4: MCU (R265.1 U5.P8), ExtensionConnector (CN5.25)
PJ5: MCU (R313.1 U5.N12), ExtensionConnector (CN6.55)
PJ6: MCU (R317.1 U5.K14), ExtensionConnector (CN5.58)
PJ7: MCU (R64.2 R315.1 U5.K15), ExtensionConnector (CN5.57)
PJ8: MCU (R306.1 U5.J15), ExtensionConnector (CN5.53)
PJ9: MCU (R310.1 U5.J14), ExtensionConnector (CN5.55)
PJ10: MCU (R312.1 U5.J13), ExtensionConnector (CN5.56)
PJ11: MCU (R302.1 U5.J11), ExtensionConnector (CN5.52)
PJ12: MCU (R34.2 R259.1 U5.E9), ExtensionConnector (CN5.24)
PJ13: MCU (R264.1 U5.D9), ExtensionConnector (CN5.26)
PJ14: MCU (R269.1 U5.C9), ExtensionConnector (CN5.28)
PJ15: MCU (R276.1 U5.B9), ExtensionConnector (CN5.29)
PK0: MCU (R305.1 U5.J12), ExtensionConnector (CN5.54)
PK1: MCU (R299.1 U5.H15), ExtensionConnector (CN5.47)
PK2: MCU (R303.1 U5.H14), ExtensionConnector (CN5.51)
PK3: MCU (R256.1 U5.B7), ExtensionConnector (CN5.21)
PK4: MCU (R254.1 U5.C7), ExtensionConnector (CN5.20)
PK5: MCU (R249.1 U5.A6), ExtensionConnector (CN5.17)
PK6: MCU (R243.1 U5.B6), ExtensionConnector (CN5.15)
PK7: MCU (R248.1 U5.D7), ExtensionConnector (CN5.18)
POTENTIOMETER: MCU (JP5.1), Peripherals (R220.2)
RS232_USART_RX: MCU (SB49.1), FDCAN&RS232 (U9.17)
RS232_USART_TX: MCU (SB50.1), FDCAN&RS232 (U9.13)
SAI1_FS_A: MCU (JP26.2), Audio_Codec (R403.2)
SAI1_MCLK_A: MCU (JP14.2), Audio_Codec (R411.2)
SAI1_SCK_A: MCU (JP28.2), Audio_Codec (R405.2)
SAI1_SD_A: MCU (JP27.2), Audio_Codec (R404.2)
SAI1_SD_B: MCU (JP34.2), Audio_Codec (R413.2)
SD_DETECT2: SDcard (JP13.2 R298.1), MCU (R297.2)
SD_LDO_SEL: MCU (JP23.3), Power_Board (R199.2 U2.6)
SDIO1_CK: SDcard (CN28.5 U38.1 U38.10), MCU (R54.1)
SDIO1_CMD: SDcard (CN28.3 R231.1 U38.2 U38.9), MCU (R49.2)
SDIO1_D0: SDcard (CN28.7 R242.1 U40.2 U40.9), MCU (JP12.1)
SDIO1_D1: SDcard (CN28.8 R247.1 U40.1 U40.10), MCU (R62.1)
SDIO1_D2: SDcard (CN28.1 R224.1 U38.5 U38.6), MCU (R56.1)
SDIO1_D3: SDcard (CN28.2 R227.1 U38.4 U38.7), MCU (R51.1)
SDIO2_CK: SDcard (CN3.5 U3.1 U3.10), MCU (JP4.3)
SDIO2_CMD: SDcard (CN3.3 R12.1 U3.2 U3.9), MCU (R289.2)
SDIO2_D0: SDcard (CN3.7 R13.1 U4.2 U4.9), MCU (JP17.3)
SDIO2_D1: SDcard (CN3.8 R14.1 U4.1 U4.10), MCU (JP2.3)
SDIO2_D2: SDcard (CN3.1 R10.1 U3.5 U3.6), MCU (JP1.3)
SDIO2_D3: SDcard (CN3.2 R11.1 U3.4 U3.7), MCU (R122.1)
SDR_CKE1: MCU (R320.1), Memory (R397.1)
SDR_CLK: MCU (R132.1), Memory (U16.J1)
SDR_NCAS: MCU (R352.1), Memory (U16.K7)
SDR_NE1: MCU (R68.1), Memory (U16.J8)
SDR_NRAS: MCU (R332.2), Memory (U16.J9)
SDR_NWE: MCU (R322.1), Memory (U16.K8)
T_VCP_RX: MCU (JP20.1 JP39.1 SB48.2 SB49.2), JTAG&Trace (SB52.2), STLink_V3E_SWD (SB41.2)
T_VCP_TX: MCU (JP21.1 JP40.1 SB47.2 SB50.2), JTAG&Trace (SB51.1), STLink_V3E_SWD (SB42.2)
TAMPER_KEY: MCU (R16.1), Peripherals (B3.1 B3.2 R194.1 U35.1)
TRACECLK: MCU (R101.1), JTAG&Trace (CN15.12 U44.1)
TRACED0: MCU (R93.1), JTAG&Trace (CN15.14 R390.1 U42.5)
TRACED1: MCU (R340.1), JTAG&Trace (CN15.16 R372.1 U42.4)
TRACED2: MCU (R71.1), JTAG&Trace (CN15.18 U42.3)
TRACED3: MCU (R80.1), JTAG&Trace (CN15.20 U42.1)
TRGIN: MCU (R64.1), JTAG&Trace (SB43.2)
TRGOUT: MCU (R34.1), JTAG&Trace (SB44.2)
ULPI_CK: MCU (JP11.3), USB_OTG_HS_externalPHY (U7.1)
ULPI_D0: MCU (JP9.3), USB_OTG_HS_externalPHY (U7.3)
ULPI_D1: MCU (JP10.2), USB_OTG_HS_externalPHY (U7.4)
ULPI_D2: MCU (R296.1), USB_OTG_HS_externalPHY (U7.5)
ULPI_D3: MCU (R292.1), USB_OTG_HS_externalPHY (U7.6)
ULPI_D4: MCU (R295.1), USB_OTG_HS_externalPHY (U7.7)
ULPI_D5: MCU (JP19.3), USB_OTG_HS_externalPHY (U7.9)
ULPI_D6: MCU (R316.1), USB_OTG_HS_externalPHY (U7.10)
ULPI_D7: MCU (JP16.1), USB_OTG_HS_externalPHY (U7.13)
ULPI_DIR: MCU (R245.1), USB_OTG_HS_externalPHY (U7.31)
ULPI_NXT: MCU (R261.1), USB_OTG_HS_externalPHY (U7.2)
ULPI_STP: MCU (R255.1), USB_OTG_HS_externalPHY (U7.29)
USB_OTG_FS_ID: MCU (R58.1), USB_OTG_FS (CN27.4 U34.1)
USB_OTG_FS_N: MCU (R63.1 SB36.2), USB_OTG_FS (U30.1)
USB_OTG_FS_OVCR: MCU (R29.1), USB_OTG_FS (LD10.2 R193.1 U29.3)
USB_OTG_FS_P: MCU (R61.1 SB35.2), USB_OTG_FS (U30.3)
USB_OTG_FS_VBUS: MCU (R60.1), USB_OTG_FS (6 pins)
USB_OTG_HS_OVCR: MCU (R108.1), USB_OTG_HS_externalPHY (LD5.2 U39.3)
WIFI_SPI4_MISO: MCU (R69.1), Peripherals (U24.11)
WIFI_SPI4_MOSI: MCU (R334.1), Peripherals (U24.8)
WIFI_SPI4_NSS: MCU (R337.1), Peripherals (U24.9)
WIFI_SPI4_SCK: MCU (R343.1), Peripherals (U24.10)
WIFI_UART_RX: MCU (SB48.1), Peripherals (U24.35)
WIFI_UART_TX: MCU (SB47.1), Peripherals (U24.34)

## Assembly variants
H7B3LIQ: not fitted C5 C6 C7 C8 C9 C11 C14 C15 C16 C21 C25 C26 C29 C78 C96 C96 C104 C200 C201 CN19 CN25 CN26 HW29 HW30 HW46 HW51 HW52 JP38 R15 R25 R26 R27 R30 R33 R34 R39 R47 R50 R55 R64 R67 R71 R72 R75 R76 R77 R78 R80 R81 R82 R88 R89 R93 R95 R97 R98 R100 R101 R106 R108 R115 R123 R125 R126 R129 R152 R156 R158 R166 R171 R173 R174 R194 R201 R202 R205 R206 R207 R208 R209 R210 R213 R219 R233 R235 R238 R239 R240 R246 R251 R253 R257 R258 R262 R268 R273 R277 R278 R281 R282 R284 R287 R288 R294 R298 R301 R304 R309 R314 R318 R319 R321 R323 R324 R330 R340 R342 R349 R354 R360 R363 R367 R372 R377 R386 R388 R389 R390 R392 R393 R394 R396 R406 R407 SB2 SB4 SB6 SB7 SB8 SB9 SB10 SB13 SB15 SB18 SB20 SB26 SB28 SB32 SB35 SB36 SB37 SB43 SB44 SB45 SB47 SB48 SB49 SB51 SB52; alternate parts JP15 -> MCD-00683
